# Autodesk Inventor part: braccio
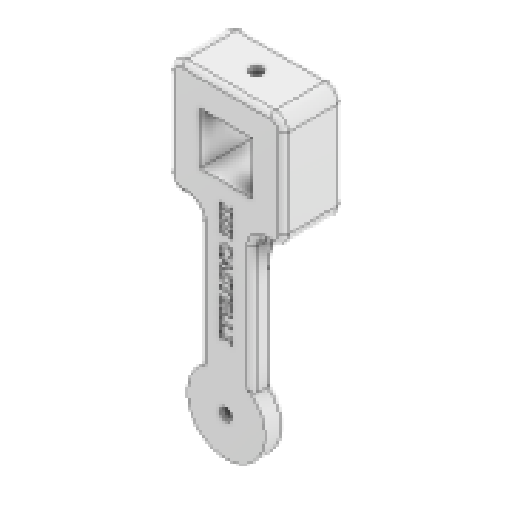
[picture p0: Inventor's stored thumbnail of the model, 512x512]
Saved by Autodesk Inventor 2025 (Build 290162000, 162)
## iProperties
Created: 2025-09
Part Number: braccio
Material: Plastica ABS
Document SubType Name: Modeling
Designer: Ryzen5700u
Density: 1.06 g/cm^3
Appearance: Liscia - Bianco
Author: Ryzen5700u
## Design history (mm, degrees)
sketch "Schizzo1"
  geometry: L1 (-10.05, -10.05)-(10.05, -10.05); L2 (10.05, -10.05)-(10.05, 10.05); L3 (10.05, 10.05)-(-10.05, 10.05); L4 (-10.05, 10.05)-(-10.05, -10.05); L5 (-10.05, -10.05)-(10.05, 10.05); L6 (10.05, -10.05)-(-10.05, 10.05); L7 (-22, -22)-(22, -22); L8 (22, -22)-(22, 22); L9 (22, 22)-(-22, 22); L10 (-22, 22)-(-22, -22); L11 (-22, -22)-(22, 22); L12 (22, -22)-(-22, 22); L13 (-10, -22)-(10, -22); L14 (10, -22)-(10, -97); L15 (10, -97)-(-10, -97); L16 (-10, -97)-(-10, -22); 2 further points
  constraints: 32 end point, 6 parallel, 4 midpoint, 3 horizontal, 3 perpendicular, 1 point on line
  dimensions: "d0" = 20.1 distance of L3.end L2.end; "d1" = 20.1 distance of L2.end L1.end; "d2" = 44 distance of L9.end L8.end; "d3" = 44 distance of L7.end L8.end; "d4" = 75 distance of L13.end L14.end
extrude "Estrusione1" new body sketch "Schizzo1" distance "d5" = 8; taper "d6" = 0 deg
sketch "Schizzo2"
  geometry: L1 (22, -22)-(10, -22) reference; L2 (22, 22)-(22, -22) reference; L3 (-22, 22)-(22, 22) reference; L4 (-22, -22)-(-22, 22) reference; L5 (-10, -22)-(-22, -22) reference; L6 (-10, -97)-(-10, -22) reference; L7 (10, -97)-(-10, -97) reference; L8 (10, -22)-(10, -97) reference; L9 (10.05, -10.05)-(10.05, 10.05) reference; L10 (-10.05, -10.05)-(10.05, -10.05) reference; L11 (-10.05, 10.05)-(-10.05, -10.05) reference; L12 (10.05, 10.05)-(-10.05, 10.05) reference; L13 (10, -22)-(-10, -22); 1 further point
  constraints: 2 end point, 1 horizontal
extrude "Estrusione2" join sketch "Schizzo2" distance "d7" = 15; taper "d8" = 0 deg
sketch "Schizzo3"
  geometry: L1 (44, 23)-(44, 0) reference; L2 (44, 23)-(0, 23) reference; L3 (44, 0)-(0, 23); L4 (0, 0)-(0, 23) reference; L5 (0, 23)-(0, 0); L6 (0, 0)-(45.029, 22.647); 2 further points
  constraints: 6 end point, 2 point on line, 1 collinear
hole "Foro1" sketch "Schizzo3" at (22.424, 11.278) diameter "d9" = 4.5; stored, may be unused: countersink angle "d13" = 90 deg, drill point angle "d15" = 118 deg; dims "d10" = 6, "d11" = 10, "d12" = 5.7, "d14" = 64.25
fillet "Raccordo1" dims "d16" = 5
sketch "Schizzo6"
  geometry: L1 (2.697, -16.966)-(2.697, -70.179); L2 (2.697, -70.179)-(-3.392, -70.179); L3 (-3.392, -70.179)-(-3.392, -16.966); L4 (-3.392, -16.966)-(2.697, -16.966); 1 further point
  constraints: 2 other
extrude "Estrusione5" cut sketch "Schizzo6" distance "d23" = 0.2; taper "d24" = 0 deg
fillet "Raccordo3" dims "d25" = 15
fillet "Raccordo6" dims "d28" = 10
sketch "Schizzo7"
  geometry: L1 (10, -87)-(10, -27) reference; L2 (15, -22)-(17, -22) reference; L3 (22, -17)-(22, 17) reference; L4 (17, 22)-(-17, 22) reference; L5 (-22, 17)-(-22, -17) reference; L6 (-17, -22)-(-15, -22) reference; L7 (-10, -27)-(-10, -87) reference; L8 (-1.448, -59.863)-(-2.4, -59.863) reference; L9 (-2.4, -59.863)-(-2.4, -56.528) reference; L10 (-2.4, -56.528)-(2.6, -56.528) reference; L11 (2.6, -56.528)-(2.6, -57.784) reference; L12 (2.6, -57.784)-(-1.448, -57.784) reference; L13 (-1.448, -57.784)-(-1.448, -59.863) reference; L14 (-2.4, -51.743)-(-2.4, -48.364) reference; L15 (-2.4, -48.364)-(2.6, -48.364) reference; L16 (2.6, -48.364)-(2.6, -51.743) reference; L17 (2.6, -51.743)-(1.647, -51.743) reference; L18 (1.647, -51.743)-(1.647, -49.612) reference; L19 (1.647, -49.612)-(0.768, -49.612) reference; L20 (0.768, -49.612)-(0.768, -51.577) reference; L21 (0.768, -51.577)-(-0.184, -51.577) reference; L22 (-0.184, -51.577)-(-0.184, -49.612) reference; L23 (-0.184, -49.612)-(-1.448, -49.612) reference; L24 (-1.448, -49.612)-(-1.448, -51.743) reference; L25 (-1.448, -51.743)-(-2.4, -51.743) reference; L26 (-2.105, -39.527)-(-0.913, -39.527) reference; L27 (-0.913, -39.527)-(-0.913, -39.64) reference; L28 (2.352, -43.311)-(1.21, -43.311) reference; L29 (1.21, -43.311)-(1.21, -43.202) reference; L30 (-2.4, -35.807)-(-2.4, -34.551) reference; L31 (-2.4, -34.551)-(2.6, -36.241) reference; L32 (2.6, -36.241)-(2.6, -37.61) reference; L33 (2.6, -37.61)-(-2.4, -39.3) reference; L34 (-2.4, -39.3)-(-2.4, -38.007) reference; L35 (-2.4, -38.007)-(-1.379, -37.695) reference; L36 (-1.379, -37.695)-(-1.379, -36.123) reference; L37 (-1.379, -36.123)-(-2.4, -35.807) reference; L38 (-2.105, -23.858)-(-0.913, -23.858) reference; L39 (-0.913, -23.858)-(-0.913, -23.972) reference; L40 (2.352, -27.643)-(1.21, -27.643) reference; L41 (1.21, -27.643)-(1.21, -27.533) reference; L42 (-1.529, -19.972)-(-2.4, -19.972) reference; L43 (-2.4, -19.972)-(-2.4, -17.282) reference; L44 (-2.4, -17.282)-(-1.529, -17.282) reference; L45 (-1.529, -17.282)-(-1.529, -17.999) reference; L46 (-1.529, -17.999)-(1.728, -17.999) reference; L47 (1.728, -17.999)-(1.728, -17.282) reference; L48 (1.728, -17.282)-(2.6, -17.282) reference; L49 (2.6, -17.282)-(2.6, -19.972) reference; L50 (2.6, -19.972)-(1.728, -19.972) reference; L51 (1.728, -19.972)-(1.728, -19.255) reference; L52 (1.728, -19.255)-(-1.529, -19.255) reference; L53 (-1.529, -19.255)-(-1.529, -19.972) reference; L54 (-1.529, -23.295)-(-2.4, -23.295) reference; L55 (-2.4, -23.295)-(-2.4, -20.604) reference; L56 (-2.4, -20.604)-(-1.529, -20.604) reference; L57 (-1.529, -20.604)-(-1.529, -21.322) reference; L58 (-1.529, -21.322)-(1.728, -21.322) reference; L59 (1.728, -21.322)-(1.728, -20.604) reference; L60 (1.728, -20.604)-(2.6, -20.604) reference; L61 (2.6, -20.604)-(2.6, -23.295) reference; L62 (2.6, -23.295)-(1.728, -23.295) reference; L63 (1.728, -23.295)-(1.728, -22.578) reference; L64 (1.728, -22.578)-(-1.529, -22.578) reference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; C1 r 15 at (0, -87); A1 r 10 centre (0, -87) between (-10, -87) and (10, -87) reference; A2 r 10 centre (0, -87) between (-10, -87) and (10, -87) reference; A3 r 5 centre (15, -27) between (15, -22) and (10, -27) reference; A4 r 5 centre (17, -17) between (17, -22) and (22, -17) reference; A5 r 5 centre (17, 17) between (22, 17) and (17, 22) reference; A6 r 5 centre (-17, 17) between (-17, 22) and (-22, 17) reference; A7 r 5 centre (-17, -17) between (-22, -17) and (-17, -22) reference; A8 r 5 centre (-15, -27) between (-10, -27) and (-15, -22) reference; 45 further points
  constraints: 1 centre point, 1 coincident, 46 other
  dimensions: "d29" = 30 diameter of C1
extrude "Estrusione6" join sketch "Schizzo7" stored distance "d30" = 10; taper "d31" = 0 deg
sketch "Schizzo8"
  geometry: A1 r 15 centre (0, -87) between (-10, -75.82) and (10, -75.82) reference; 1 further point
hole "Foro2" sketch "Schizzo8" at (0, -87) diameter "d32" = 4.5; stored, may be unused: countersink angle "d36" = 90 deg, drill point angle "d38" = 118 deg; dims "d33" = 6, "d34" = 8, "d35" = 4.6, "d37" = 8
sketch "Schizzo9"
  geometry: L1 (4.5, -87)-(2.25, -90.897); L2 (2.25, -90.897)-(-2.25, -90.897); L3 (-2.25, -90.897)-(-4.5, -87); L4 (-4.5, -87)-(-2.25, -83.103); L5 (-2.25, -83.103)-(2.25, -83.103); L6 (2.25, -83.103)-(4.5, -87); C1 r 2.25 at (0, -87) reference; 2 further points
  constraints: 12 end point, 1 coincident, 13 other
  dimensions: "d39" = 4.5 distance of L1.end L2.end
extrude "Estrusione7" cut sketch "Schizzo9" distance "d40" = 5; taper "d41" = 0 deg
fillet "Raccordo7" dims "d42" = 2
fillet "Raccordo8" dims "d43" = 2
node "Solido1"
node "Linea chiusa proiettata1"
node "Linea chiusa proiettata2"
